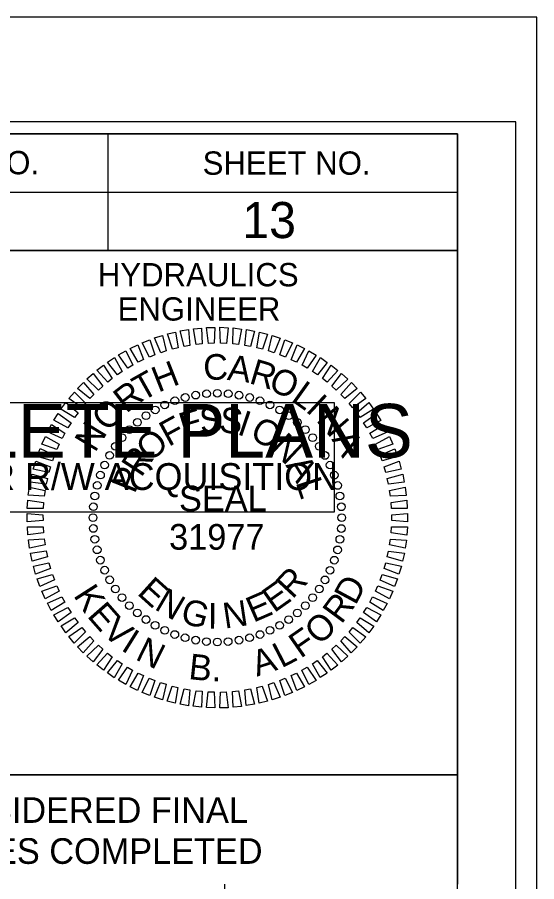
# Model space of a CAD drawing. Extents: x 557032 to 558716, y 525869 to 526969.
# Drawn here: x 558605 to 558716.5, y 526783.7 to 526969.2 of the extents above; entities that cross this region are included whole.
import ezdxf

# ---------------------------------------------------------------- set-up
doc = ezdxf.new("R2010")
doc.units = 0
for name, color, linetype in [('Default', 7, 'Continuous'), ('Sheet Cutting Line CELL', 7, 'Continuous'), ('Sheet Data Field CELL', 7, 'Continuous'), ('Sheet Plot Border Inside CELL', 7, 'Continuous'), ('Sheet Plot Border Outside CELL', 7, 'Continuous'), ('Sheet Profile CELL', 7, 'Continuous'), ('Sheet Profile Grid Major CELL', 7, 'Continuous'), ('Sheet Sticker Exception Certification CELL', 7, 'Continuous'), ('Sheet Sticker Incomplete CELL', 7, 'Continuous')]:
    doc.layers.add(name, color=color, linetype=linetype)

msp = doc.modelspace()

# ---------------------------------------------------------------- linework, layer by layer
at = {"layer": 'Default'}
for points in [[(558640.81, 526898.57), (558639.96, 526901.9), (558641.72, 526902.18), (558642.05, 526898.8)], [(558643.39, 526898.98), (558642.78, 526902.36), (558644.55, 526902.51), (558644.64, 526899.12)], [(558646, 526899.2), (558645.62, 526902.62), (558647.4, 526902.65), (558647.25, 526899.26)], [(558648.61, 526899.25), (558648.47, 526902.68), (558650.24, 526902.59), (558649.86, 526899.21)], [(558651.22, 526899.11), (558651.32, 526902.54), (558653.08, 526902.32), (558652.47, 526898.99)], [(558653.81, 526898.79), (558654.15, 526902.21), (558655.89, 526901.87), (558655.05, 526898.58)], [(558635.77, 526897.23), (558634.46, 526900.4), (558636.17, 526900.92), (558636.96, 526897.62)], [(558638.27, 526897.99), (558637.19, 526901.25), (558638.92, 526901.65), (558639.49, 526898.3)], [(558656.37, 526898.29), (558656.95, 526901.67), (558658.67, 526901.21), (558657.59, 526897.99)], [(558658.89, 526897.61), (558659.7, 526900.95), (558661.39, 526900.37), (558660.09, 526897.23)], [(558630.96, 526895.19), (558629.23, 526898.16), (558630.84, 526898.91), (558632.09, 526895.75)], [(558633.33, 526896.29), (558631.81, 526899.37), (558633.47, 526900.01), (558634.49, 526896.77)], [(558661.36, 526896.76), (558662.4, 526900.03), (558664.04, 526899.33), (558662.53, 526896.29)], [(558663.77, 526895.73), (558665.03, 526898.93), (558666.62, 526898.12), (558664.9, 526895.19)], [(558628.68, 526893.93), (558626.74, 526896.76), (558628.3, 526897.62), (558629.76, 526894.56)], [(558666.09, 526894.55), (558667.58, 526897.64), (558669.1, 526896.73), (558667.18, 526893.92)], [(558626.49, 526892.51), (558624.35, 526895.2), (558625.85, 526896.17), (558627.52, 526893.22)], [(558668.33, 526893.2), (558670.03, 526896.18), (558671.49, 526895.16), (558669.38, 526892.5)], [(558624.4, 526890.94), (558622.08, 526893.47), (558623.51, 526894.54), (558625.38, 526891.72)], [(558670.47, 526891.7), (558672.37, 526894.56), (558673.75, 526893.44), (558671.46, 526890.93)], [(558622.43, 526889.22), (558619.94, 526891.6), (558621.28, 526892.76), (558623.35, 526890.07)], [(558672.5, 526890.05), (558674.59, 526892.77), (558675.9, 526891.56), (558673.44, 526889.22)], [(558620.58, 526887.38), (558617.93, 526889.57), (558619.19, 526890.83), (558621.45, 526888.29)], [(558674.4, 526888.27), (558676.69, 526890.84), (558677.9, 526889.54), (558675.28, 526887.37)], [(558618.86, 526885.41), (558616.07, 526887.41), (558617.24, 526888.75), (558619.66, 526886.38)], [(558676.18, 526886.36), (558678.64, 526888.76), (558679.76, 526887.38), (558677, 526885.4)], [(558617.29, 526883.32), (558614.36, 526885.13), (558615.44, 526886.55), (558618.02, 526884.35)], [(558677.83, 526884.33), (558680.44, 526886.55), (558681.46, 526885.09), (558678.57, 526883.32)], [(558615.86, 526881.13), (558612.82, 526882.73), (558613.79, 526884.22), (558616.52, 526882.21)], [(558679.32, 526882.19), (558682.09, 526884.22), (558683, 526882.7), (558680, 526881.12)], [(558614.6, 526878.85), (558611.45, 526880.23), (558612.31, 526881.79), (558615.18, 526879.97)], [(558680.67, 526879.95), (558683.57, 526881.78), (558684.37, 526880.2), (558681.26, 526878.84)], [(558613.49, 526876.49), (558610.25, 526877.64), (558611.01, 526879.25), (558613.99, 526877.64)], [(558681.85, 526877.62), (558684.87, 526879.25), (558685.57, 526877.61), (558682.37, 526876.47)], [(558612.55, 526874.05), (558609.24, 526874.98), (558609.88, 526876.64), (558612.97, 526875.23)], [(558682.87, 526875.21), (558686, 526876.63), (558686.58, 526874.95), (558683.31, 526874.03)], [(558611.79, 526871.55), (558608.42, 526872.25), (558608.94, 526873.95), (558612.12, 526872.76)], [(558683.72, 526872.74), (558686.94, 526873.94), (558687.4, 526872.22), (558684.07, 526871.54)], [(558611.2, 526869.01), (558607.79, 526869.46), (558608.19, 526871.2), (558611.45, 526870.24)], [(558684.39, 526870.22), (558687.69, 526871.19), (558688.02, 526869.44), (558684.66, 526868.99)], [(558610.79, 526866.43), (558607.36, 526866.65), (558607.64, 526868.4), (558610.95, 526867.67)], [(558684.89, 526867.66), (558688.24, 526868.39), (558688.46, 526866.62), (558685.07, 526866.41)], [(558610.56, 526863.83), (558607.12, 526863.81), (558607.28, 526865.58), (558610.64, 526865.08)], [(558685.2, 526865.06), (558688.6, 526865.56), (558688.69, 526863.78), (558685.3, 526863.81)], [(558610.51, 526861.21), (558607.08, 526860.95), (558607.11, 526862.73), (558610.5, 526862.47)], [(558685.34, 526862.45), (558688.76, 526862.71), (558688.73, 526860.94), (558685.34, 526861.2)], [(558610.64, 526858.61), (558607.24, 526858.11), (558607.15, 526859.88), (558610.55, 526859.86)], [(558685.29, 526859.84), (558688.72, 526859.86), (558688.57, 526858.09), (558685.21, 526858.59)], [(558610.96, 526856.01), (558607.6, 526855.28), (558607.39, 526857.04), (558610.77, 526857.26)], [(558685.06, 526857.24), (558688.49, 526857.02), (558688.21, 526855.27), (558684.89, 526856)], [(558611.45, 526853.45), (558608.16, 526852.48), (558607.82, 526854.23), (558611.18, 526854.68)], [(558684.65, 526854.66), (558688.05, 526854.2), (558687.65, 526852.47), (558684.39, 526853.43)], [(558612.13, 526850.93), (558608.91, 526849.73), (558608.45, 526851.45), (558611.77, 526852.13)], [(558684.06, 526852.12), (558687.42, 526851.42), (558686.9, 526849.72), (558683.72, 526850.91)], [(558612.98, 526848.46), (558609.85, 526847.04), (558609.27, 526848.72), (558612.54, 526849.63)], [(558683.29, 526849.62), (558686.6, 526848.69), (558685.96, 526847.03), (558682.87, 526848.44)], [(558613.99, 526846.05), (558610.97, 526844.42), (558610.28, 526846.06), (558613.48, 526847.2)], [(558682.35, 526847.18), (558685.59, 526846.03), (558684.84, 526844.42), (558681.85, 526846.03)], [(558615.18, 526843.72), (558612.28, 526841.88), (558611.47, 526843.47), (558614.58, 526844.83)], [(558681.25, 526844.82), (558684.39, 526843.44), (558683.53, 526841.88), (558680.66, 526843.7)], [(558616.52, 526841.48), (558613.75, 526839.45), (558612.84, 526840.97), (558615.85, 526842.54)], [(558679.98, 526842.53), (558683.02, 526840.94), (558682.05, 526839.45), (558679.32, 526841.46)], [(558618.02, 526839.34), (558615.4, 526837.12), (558614.38, 526838.58), (558617.27, 526840.35)], [(558678.56, 526840.34), (558681.48, 526838.54), (558680.41, 526837.12), (558677.82, 526839.32)], [(558619.66, 526837.31), (558617.2, 526834.91), (558616.08, 526836.29), (558618.84, 526838.27)], [(558676.98, 526838.26), (558679.77, 526836.26), (558678.6, 526834.92), (558676.18, 526837.29)], [(558621.44, 526835.4), (558619.16, 526832.83), (558617.94, 526834.13), (558620.56, 526836.3)], [(558675.27, 526836.29), (558677.91, 526834.1), (558676.65, 526832.84), (558674.4, 526835.38)], [(558623.35, 526833.62), (558621.25, 526830.9), (558619.95, 526832.11), (558622.41, 526834.45)], [(558673.42, 526834.45), (558675.9, 526832.07), (558674.56, 526830.91), (558672.49, 526833.6)], [(558625.38, 526831.97), (558623.47, 526829.11), (558622.09, 526830.23), (558624.38, 526832.74)], [(558671.45, 526832.73), (558673.76, 526830.19), (558672.34, 526829.12), (558670.46, 526831.95)], [(558627.51, 526830.47), (558625.81, 526827.48), (558624.36, 526828.51), (558626.47, 526831.17)], [(558669.36, 526831.16), (558671.49, 526828.47), (558670, 526827.5), (558668.32, 526830.45)], [(558629.75, 526829.12), (558628.26, 526826.03), (558626.74, 526826.94), (558628.66, 526829.74)], [(558632.08, 526827.93), (558630.81, 526824.74), (558629.22, 526825.55), (558630.94, 526828.48)], [(558664.88, 526828.48), (558666.62, 526825.51), (558665, 526824.76), (558663.75, 526827.92)], [(558667.17, 526829.74), (558669.1, 526826.91), (558667.55, 526826.04), (558666.08, 526829.11)], [(558634.48, 526826.91), (558633.44, 526823.64), (558631.8, 526824.33), (558633.31, 526827.38)], [(558636.95, 526826.06), (558636.14, 526822.72), (558634.46, 526823.3), (558635.75, 526826.44)], [(558660.07, 526826.44), (558661.38, 526823.27), (558659.68, 526822.75), (558658.88, 526826.05)], [(558662.51, 526827.38), (558664.04, 526824.3), (558662.38, 526823.66), (558661.35, 526826.9)], [(558639.47, 526825.38), (558638.9, 526821.99), (558637.18, 526822.46), (558638.25, 526825.68)], [(558642.04, 526824.88), (558641.7, 526821.46), (558639.95, 526821.8), (558640.8, 526825.09)], [(558644.63, 526824.56), (558644.53, 526821.13), (558642.76, 526821.34), (558643.38, 526824.68)], [(558647.24, 526824.42), (558647.38, 526820.99), (558645.6, 526821.08), (558645.98, 526824.46)], [(558649.85, 526824.46), (558650.23, 526821.05), (558648.45, 526821.02), (558648.59, 526824.41)], [(558652.45, 526824.69), (558653.07, 526821.31), (558651.29, 526821.16), (558651.2, 526824.55)], [(558655.03, 526825.1), (558655.88, 526821.77), (558654.12, 526821.49), (558653.79, 526824.87)], [(558657.57, 526825.68), (558658.66, 526822.42), (558656.92, 526822.02), (558656.36, 526825.37)]]:
    msp.add_lwpolyline(points, close=True, dxfattribs=at)
for centre in [(558645.6, 526888.43), (558647.93, 526888.53), (558650.25, 526888.43), (558638.8, 526886.92), (558641.02, 526887.62), (558643.29, 526888.13), (558652.56, 526888.12), (558654.84, 526887.62), (558657.06, 526886.92), (558634.58, 526884.96), (558636.64, 526886.03), (558659.21, 526886.03), (558661.27, 526884.95), (558632.61, 526883.71), (558663.24, 526883.7), (558630.77, 526882.29), (558665.09, 526882.28), (558629.05, 526880.72), (558666.8, 526880.71), (558627.47, 526879), (558668.38, 526878.99), (558626.06, 526877.15), (558669.79, 526877.14), (558624.8, 526875.19), (558671.04, 526875.18), (558623.73, 526873.12), (558672.12, 526873.11), (558622.84, 526870.97), (558673.01, 526870.96), (558622.14, 526868.75), (558673.71, 526868.74), (558621.63, 526866.48), (558674.21, 526866.47), (558621.33, 526864.17), (558674.52, 526864.16), (558621.23, 526861.84), (558674.62, 526861.83), (558621.33, 526859.51), (558674.52, 526859.5), (558621.63, 526857.2), (558674.21, 526857.19), (558622.13, 526854.93), (558673.71, 526854.92), (558622.83, 526852.71), (558673.01, 526852.7), (558623.72, 526850.56), (558672.11, 526850.55), (558624.8, 526848.49), (558671.04, 526848.48), (558626.05, 526846.53), (558669.79, 526846.52), (558627.47, 526844.68), (558668.37, 526844.67), (558629.04, 526842.96), (558666.8, 526842.95), (558630.76, 526841.39), (558665.08, 526841.38), (558632.61, 526839.97), (558634.57, 526838.72), (558661.27, 526838.71), (558663.23, 526839.96), (558636.63, 526837.64), (558638.79, 526836.75), (558657.05, 526836.75), (558659.2, 526837.64), (558641.01, 526836.05), (558643.28, 526835.54), (558645.59, 526835.24), (558647.92, 526835.14), (558650.24, 526835.24), (558652.55, 526835.54), (558654.83, 526836.05)]:
    msp.add_circle(centre, 0.826, dxfattribs=at)
at = {"layer": 'Sheet Cutting Line CELL'}
msp.add_line((558716.45, 526969.22), (557032.45, 526969.22), dxfattribs=at)
at = {"layer": 'Sheet Plot Border Inside CELL'}
msp.add_lwpolyline([(557045.45, 525891.67), (558711.95, 525891.67), (558711.95, 526946.77), (557045.45, 526946.77)], close=True, dxfattribs=at)
at = {"layer": 'Sheet Plot Border Outside CELL'}
msp.add_lwpolyline([(557032.45, 525869.22), (558716.45, 525869.22), (558716.45, 526969.22), (557032.45, 526969.22)], close=True, dxfattribs=at)
at = {"layer": 'Sheet Profile CELL'}
for p, q in [((558624.45, 526944.17), (558624.45, 526919.17)), ((558499.4, 526931.67), (558699.45, 526931.67))]:
    msp.add_line(p, q, dxfattribs=at)
for points in [[(558699.45, 526944.22), (557199.45, 526944.22), (557199.45, 525894.22), (558699.45, 525894.22)], [(558499.4, 526944.22), (558699.45, 526944.22), (558699.45, 526919.17), (558499.4, 526919.17)], [(558599.45, 526919.17), (558699.45, 526919.17), (558699.45, 526806.67), (558599.45, 526806.67)]]:
    msp.add_lwpolyline(points, close=True, dxfattribs=at)
at = {"layer": 'Sheet Profile Grid Major CELL'}
msp.add_lwpolyline([(558649.45, 526783.17), (558649.45, 526444.22), (558699.45, 526444.22), (558699.45, 526794.22)], dxfattribs=at)
at = {"layer": 'Sheet Sticker Exception Certification CELL'}
for p, q in [((558499.4, 526806.67), (558699.44, 526806.67)), ((558499.4, 526806.67), (558699.44, 526806.67)), ((558699.44, 526806.66), (558699.44, 526783.16)), ((558699.44, 526806.66), (558699.44, 526783.16))]:
    msp.add_line(p, q, dxfattribs=at)
at = {"layer": 'Sheet Sticker Incomplete CELL'}
msp.add_lwpolyline([(558525.97, 526863.02), (558525.97, 526886.52), (558672.97, 526886.52), (558672.97, 526863.02)], close=True, dxfattribs=at)

# ---------------------------------------------------------------- texts
at = {"layer": 'Default'}
for s, height, rotation, p in [('C', 5.5, 1.9509, (558644.99, 526891.34)), ('A', 5.5, 352.4458, (558649.9, 526891.42)), ('H', 5.5, 21.5901, (558635.24, 526888.64)), ('R', 5.5, 343.3983, (558654.53, 526890.74)), ('T', 5.5, 29.3793, (558631.73, 526886.67)), ('O', 5.5, 335.1897, (558658.59, 526889.5)), ('L', 5.5, 324.4645, (558663.55, 526887.03)), ('R', 5.5, 37.5879, (558628.35, 526884.1)), ('I', 5.5, 316.9994, (558666.69, 526884.79)), ('O', 5.5, 48.3131, (558624.55, 526880.07)), ('S', 5.5, 5.2127, (558644.34, 526879.89)), ('S', 5.5, 353.2538, (558648.16, 526880.24)), ('N', 5.5, 311.0594, (558668.96, 526882.72)), ('F', 5.5, 28.6529, (558637.46, 526876.97)), ('E', 5.5, 16.975, (558640.74, 526878.78)), ('I', 5.5, 341.2948, (558651.97, 526879.79)), ('N', 5.5, 58.5235, (558621.68, 526875.64)), ('O', 5.5, 332.5394, (558654.65, 526878.96)), ('O', 5.5, 44.4617, (558633.73, 526873.55)), ('N', 5.5, 316.7306, (558659.06, 526876.48)), ('A', 5.5, 300.849, (558672.33, 526878.66)), ('R', 5.5, 56.5612, (558631.59, 526870.31)), ('P', 5.5, 68.3234, (558630.2, 526866.8)), ('A', 5.5, 301.6806, (558662.48, 526873.09)), ('SEAL', 5.504, 359.989, (558639.69, 526863.21)), ('L', 5.5, 288.3447, (558664.69, 526869.42)), ('31977', 5.504, 359.989, (558637.57, 526854.96)), ('R', 5.5, 47.032, (558664.03, 526844.2)), ('E', 5.5, 317.8396, (558630.51, 526845.48)), ('E', 5.5, 35.2697, (558660.1, 526841.29)), ('D', 5.5, 61.6895, (558677.55, 526842.85)), ('K', 5.5, 302.6028, (558616.92, 526845.17)), ('N', 5.5, 329.6019, (558634.21, 526842.28)), ('E', 5.5, 23.5075, (558655.65, 526839.24)), ('R', 5.5, 53.4809, (558674.54, 526838.81)), ('E', 5.5, 311.3071, (558619.8, 526840.67)), ('G', 5.5, 344.6519, (558639.76, 526839.39)), ('I', 5.5, 359.702, (558645.87, 526838.04)), ('N', 5.5, 8.4574, (558649.52, 526838)), ('V', 5.5, 319.287, (558623.01, 526836.97)), ('O', 5.5, 42.7557, (558669.79, 526834.26)), ('I', 5.5, 327.9723, (558627.05, 526833.5)), ('F', 5.5, 34.833, (558665.78, 526831.51)), ('N', 5.5, 333.9122, (558630.1, 526831.49)), ('A', 5.5, 18.3204, (558656.42, 526827.68)), ('L', 5.5, 27.3679, (558661.69, 526829.45)), ('B', 5.5, 354.009, (558641.61, 526827.21)), ('.', 5.5, 2.3511, (558646.7, 526826.66))]:
    msp.add_text(s, height=height, rotation=rotation, dxfattribs=at).set_placement(p)
at = {"layer": 'Sheet Data Field CELL'}
msp.add_text('13 ', height=7.75, dxfattribs=at).set_placement((558653.27, 526921.83))
at = {"layer": 'Sheet Profile CELL'}
for s, height, p in [('PROJECT REFERENCE NO.', 5.0001, (558521.62, 526935.53)), ('SHEET NO.', 5, (558644.77, 526935.43)), ('HYDRAULICS', 5, (558622.27, 526911.48)), ('ENGINEER', 5, (558626.52, 526904.13))]:
    msp.add_text(s, height=height, dxfattribs=at).set_placement(p)
at = {"layer": 'Sheet Sticker Exception Certification CELL'}
for s, p in [('DOCUMENT NOT CONSIDERED FINAL', (558520.47, 526796.33)), ('DOCUMENT NOT CONSIDERED FINAL', (558520.47, 526796.33)), ('UNLESS ALL SIGNATURES COMPLETED', (558515.4, 526787.53)), ('UNLESS ALL SIGNATURES COMPLETED', (558515.4, 526787.53))]:
    msp.add_text(s, height=5.5, dxfattribs=at).set_placement(p)
at = {"layer": 'Sheet Sticker Incomplete CELL'}
for s, height, p in [('INCOMPLETE PLANS', 11.52, (558534.92, 526874.72)), ('DO NOT USE FOR R/W ACQUISITION', 5.76, (558538.17, 526867.77))]:
    msp.add_text(s, height=height, dxfattribs=at).set_placement(p)

doc.saveas('drawing.dxf')
